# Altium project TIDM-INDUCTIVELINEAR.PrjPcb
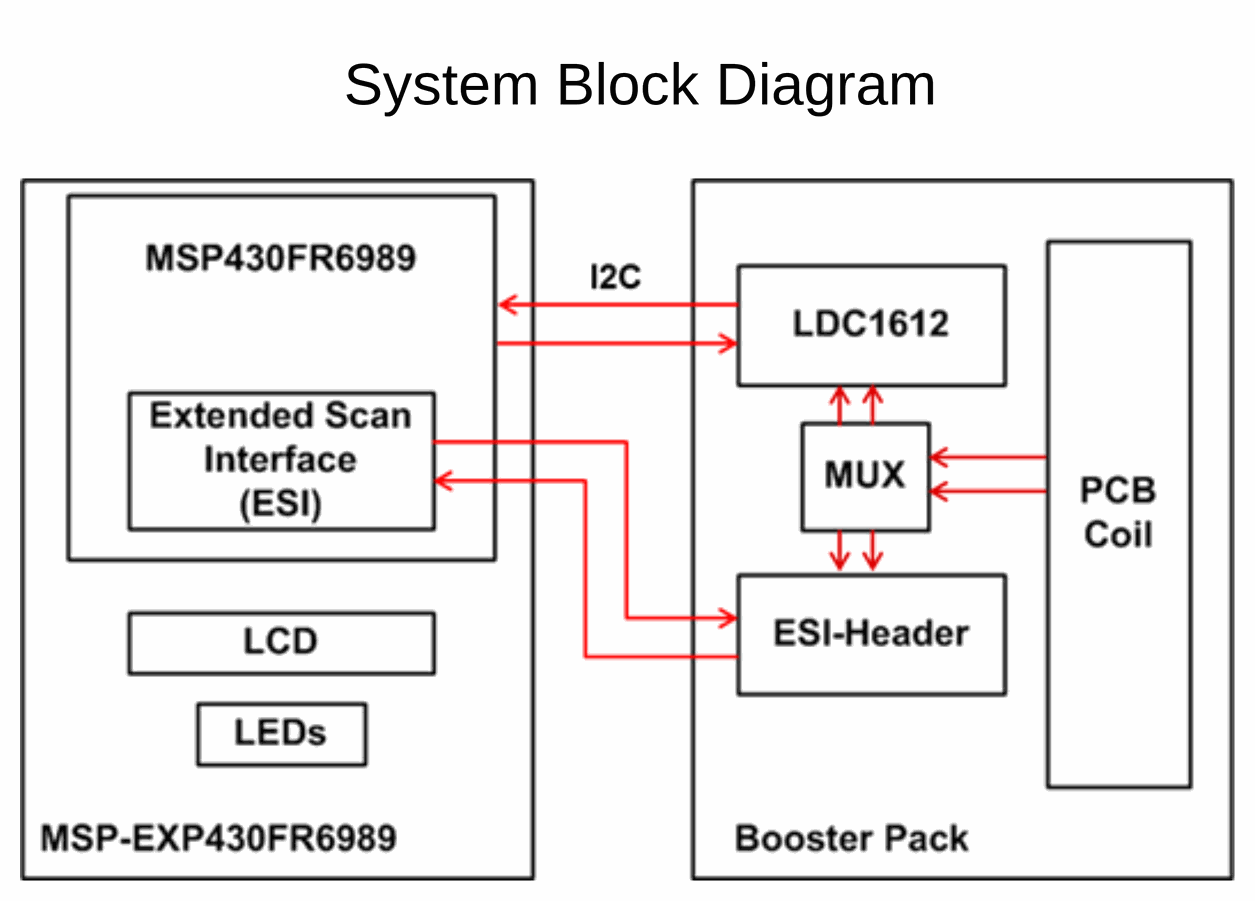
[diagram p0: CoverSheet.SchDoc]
CopyrightYear: 2015; EVM_Orderable: N/A; PCB_Layout: a0225755; PCB_Rev: 1.0; PRJ_Customer: Public Release; PRJ_Engineer: a0225755; PRJ_TITLE: TIDM_INDUCTIVELINEAR; SCH_Rev: 1.0; TechSupport: http://www.ti.com/support; TID: TIDM-INDUCTIVELINEAR
2 sheets, 26 parts. Net scope: global (net labels, ports and power ports of the same name join across sheets).
Board file: TIDM-INDUCTIVELINEAR.PcbDoc
Sheets:
  CoverSheet.SchDoc
  Schematics.SchDoc

## Sheet CoverSheet.SchDoc
size 431 x 279 mm; Date: Not shown in title block; ApprovedBy: Not shown in title block; CheckedBy: Not shown in title block; Author: Not shown in title block; CompanyName: Not shown in title block; Engineer: Not shown in title block; Organization: Not shown in title block; Address1: Not shown in title block; Address2: Not shown in title block; Address3: Not shown in title block; Address4: Not shown in title block; DocumentNumber: 1; Revision: Use project parameter SCH_Rev; SheetNumber: 1; SheetTotal: 2; PageSetup: Record=PageOptions|CenterHorizontal=True|CenterVertical=True|PrintScale=1.00|XCorrection=1.00|YCorrection=1.00|PrintKind=0|BorderSize=5000000|LeftOffset=0|BottomOffset=0|Orientation=2|PaperLength=1000|PaperWidth=1000|Scale=100|PaperSource=15|PrintQuality=600|MediaType=1|DitherType=10|PaperKind=Letter|PrintScaleMode=1

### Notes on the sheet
- System Block Diagram

## Sheet Schematics.SchDoc
size 431 x 279 mm; VersionControl_RevNumber: Not shown in title block; Date: Not shown in title block; ApprovedBy: Not shown in title block; CheckedBy: Not shown in title block; Author: Not shown in title block; CompanyName: Not shown in title block; Engineer: Not shown in title block; Organization: Not shown in title block; Address1: Not shown in title block; Address2: Not shown in title block; Address3: Not shown in title block; Address4: Not shown in title block; DocumentNumber: 1; Revision: Use project parameter SCH_Rev; SheetNumber: 2; SheetTotal: 2; PageSetup: Record=PageOptions|CenterHorizontal=True|CenterVertical=True|PrintScale=1.00|XCorrection=1.00|YCorrection=1.00|PrintKind=0|BorderSize=5000000|LeftOffset=0|BottomOffset=0|Orientation=2|PaperLength=1000|PaperWidth=1000|Scale=100|PaperSource=15|PrintQuality=600|MediaType=1|DitherType=10|PaperKind=Letter|PrintScaleMode=1
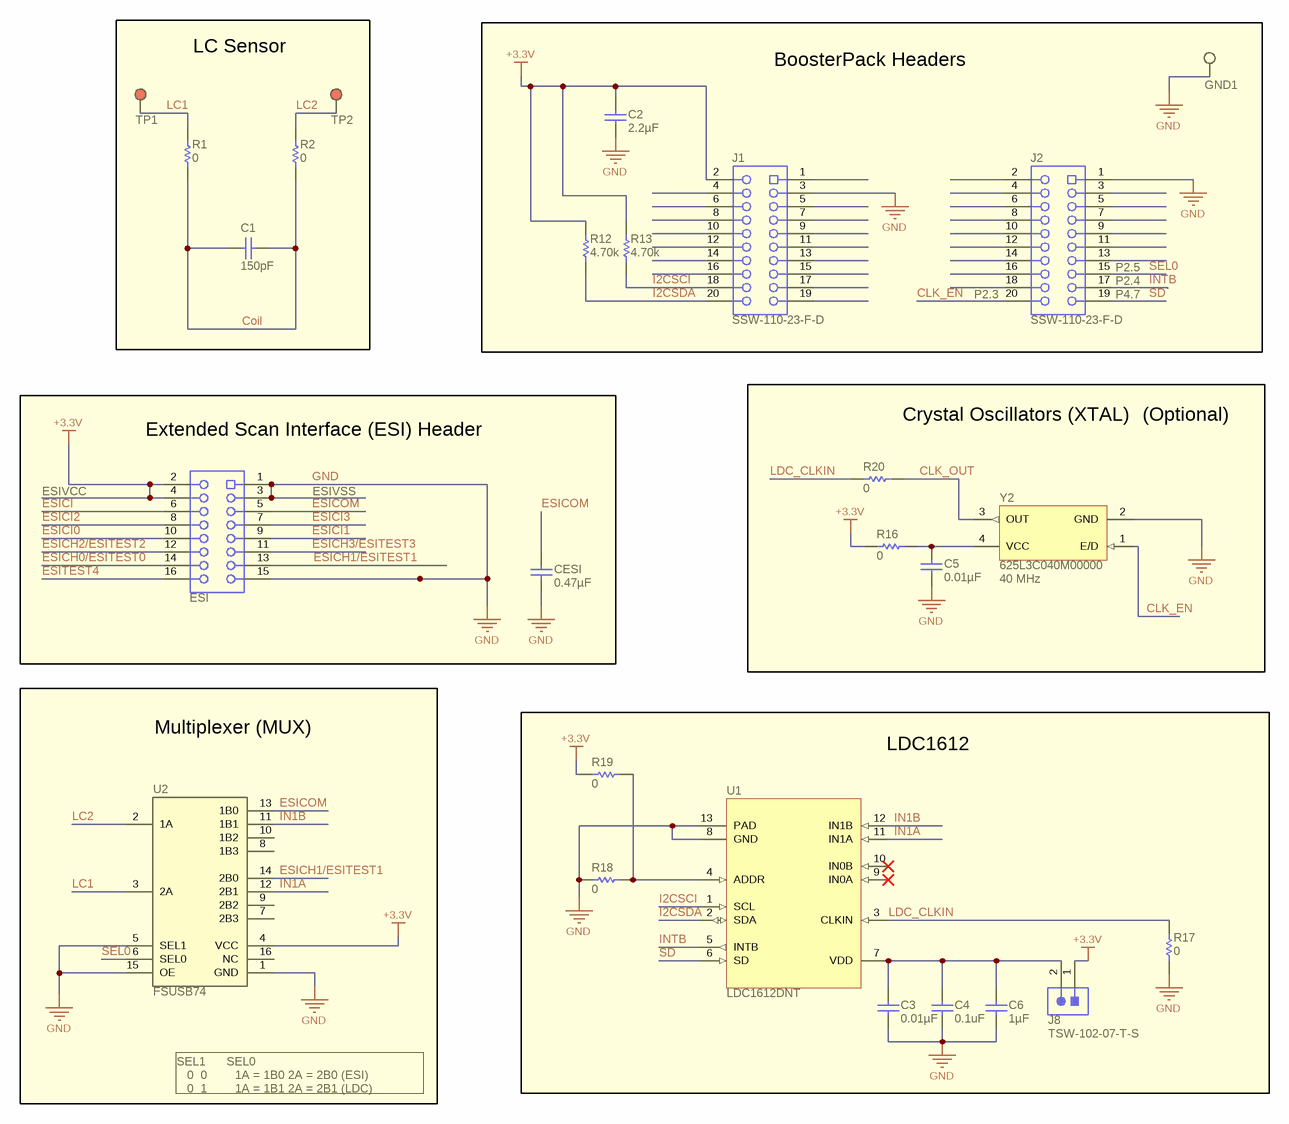
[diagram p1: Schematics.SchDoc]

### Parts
C1  ValueDisplayed: 150pF  [0603]  (hidden comment: GRM1885C2A151JA01D)
C2  ValueDisplayed: 2.2µF  [0603]  (hidden comment: C0603C225K8PACTU)
C3  ValueDisplayed: 0.01µF  [0402]  (hidden comment: C1005X7R1C103K)
C4  value 0.1uF  [0402]  (hidden comment: GRM155R71C104JA88D)
C5  ValueDisplayed: 0.01µF  [0603]  (hidden comment: C1608C0G1E103J)
C6  ValueDisplayed: 1µF  [0402]  (hidden comment: GRM155R61A105KE15D)
CESI  ValueDisplayed: 0.47µF  [0603]  (hidden comment: GRM188R61A474KA61D)
ESI  SSQ-108-02-G-D  [SAMTEC_SSQ-108-02-G-D]  (value not drawn)
GND1  5016  [Testpoint_Keystone_Compact]  (value not drawn)
J1  SSW-110-23-F-D  [CONN_SSW-110-23-F-D]
J2  SSW-110-23-F-D  [CONN_SSW-110-23-F-D]
J8  TSW-102-07-T-S  [Samtec_TSW-102-07-T-S]
R1  ValueDisplayed: 0  [0805_HV]  (hidden comment: ERJ-6GEY0R00V)
R2  ValueDisplayed: 0  [0805_HV]  (hidden comment: ERJ-6GEY0R00V)
R12  value 4.70k  [0603]  (hidden comment: RC0603FR-074K7L)
R13  value 4.70k  [0603]  (hidden comment: RC0603FR-074K7L)
R16  value 0  [0603]  (hidden comment: CRCW06030000Z0EA)
R17  value 0  [0603]  (hidden comment: CRCW06030000Z0EA)
R18  value 0  [0603]  (hidden comment: CRCW06030000Z0EA)
R19  value 0  [0603]  (hidden comment: CRCW06030000Z0EA)
R20  value 0  [0603]  (hidden comment: CRCW06030000Z0EA)
TP1  5000  [Keystone5000]  (value not drawn)
TP2  5000  [Keystone5000]  (value not drawn)
U1  LDC1612DNT  [DNT0012B]
U2  FSUSB74  [LCCS40P210X290X55-16N]
Y2  625L3C040M00000  Frequency: 40 MHz  [OSC_CTS_625]

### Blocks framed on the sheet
LC Sensor: C1 R1 R2 TP1 TP2
BoosterPack Headers: C2 GND1 J1 J2 R12 R13
Extended Scan Interface (ESI) Header: CESI ESI
Multiplexer (MUX): U2
LDC1612: C3 C4 C6 J8 R17-R19 U1

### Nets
+3.3V: C2.1 ESI.2 ESI.4 J1.2 J8.1 R12.2 R13.2 R16.2 R19.2 U2.4(VCC)
GND: C2.2 C3.2 C4.2 C5.2 C6.2 CESI.2 ESI.1 ESI.3 ESI.15 GND1.1 J1.3 J2.1 R17.2 R18.2 U1.8(GND) U1.13(PAD) U2.1(GND) U2.5(SEL1) U2.15(OE) Y2.2(GND)
CLK_EN: J2.20 Y2.1(E/D)
CLK_OUT: R20.1 Y2.3(OUT)
Coil: C1.1 C1.2 R1.1 R2.1
ESICH0/ESITEST0: ESI.14
ESICH1/ESITEST1: ESI.13 U2.14(2B0)
ESICH2/ESITEST2: ESI.12
ESICH3/ESITEST3: ESI.11
ESICI: ESI.6
ESICI0: ESI.10
ESICI1: ESI.9
ESICI2: ESI.8
ESICI3: ESI.7
ESICOM: CESI.1 ESI.5 U2.13(1B0)
ESITEST4: ESI.16
I2CSCI: J1.18 R13.1 U1.1(SCL)
I2CSDA: J1.20 R12.1 U1.2(SDA)
IN1A: U1.11(IN1A) U2.12(2B1)
IN1B: U1.12(IN1B) U2.11(1B1)
INTB: J2.17 U1.5(INTB)
LC1: R1.2 TP1.1 U2.3(2A)
LC2: R2.2 TP2.1 U2.2(1A)
LDC_CLKIN: R17.1 R20.2 U1.3(CLKIN)
SD: J2.19 U1.6(SD)
SEL0: J2.15 U2.6(SEL0)
NetC3_1: C3.1 C4.1 C6.1 J8.2 U1.7(VDD)
NetC5_1: C5.1 R16.1 Y2.4(VCC)
NetR18_1: R18.1 R19.1 U1.4(ADDR)

Not connected (* = marked no-connect by the designer): J1 1 4 5 6 7 8 9 10 11 12 13 14 15 16 17 19; J2 2 3 4 5 6 7 8 9 10 11 12 13 14 16 18; U1 9(IN0A)* 10(IN0B)*; U2 7(2B3) 8(1B3) 9(2B2) 10(1B2) 16(NC)

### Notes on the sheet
- (near J2) P2.4
- (near J2) P2.5
- (near J2) P2.3
- (near J2) P4.7
- Crystal Oscillators (XTAL)
- (Optional)
- ESIVCC
- ESIVSS
- SEL1      SEL0
  0	 0        1A = 1B0 2A = 2B0 (ESI)
  0	 1        1A = 1B1 2A = 2B1 (LDC)

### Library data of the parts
C1 = GRM1885C2A151JA01D: CAP, CERM, 150 pF, 100 V, +/- 5%, C0G/NP0, 0603; Manufacturer: MuRata; Polarized: N; CompType: Capacitor; Value: 150pF; U/M: EA; Cap_F: 0.00000000015; Tolerance_%: 5; Value1: Unknown; VDC_V: 100; Value2: 100V; TaMin_C: -55; TaMax_C: 125
C2 = C0603C225K8PACTU: CAP, CERM, 2.2uF, 10V, +/-10%, X5R, 0603; Manufacturer: Kemet; Polarized: N; CompType: Capacitor; U/M: EA; Cap_F: 0.0000022; Tolerance_%: 10; Value1: Unknown; TaMin_C: -55; TaMax_C: 85
C3 = C1005X7R1C103K: CAP, CERM, 0.01 µF, 16 V, +/- 10%, X7R, 0402; Manufacturer: TDK; Polarized: N; CompType: Capacitor; Value: 0.01uF; U/M: EA; Cap_F: 0.00000001; Tolerance_%: 10; ESR_ohm: 0.0623; Value1: 0.0623 ohm; VDC_V: 16; Value2: 16V; TaMin_C: -55; TaMax_C: 125
C4 = 0402YC132KAT2A: CAP CER 0.1UF 16V 5% X7R 0402; Manufacturer: Murata Electronics North America; Polarized: N; CompType: Capacitor; U/M: EA; Cap_F: 0.0000000013; Tolerance_%: 10; VDC_V: 16; TaMin_C: -55; TaMax_C: 125
C5 = C1608C0G1E103J: CAP, CERM, 0.01uF, 25V, +/-5%, C0G/NP0, 0603; Manufacturer: TDK; Polarized: N; CompType: Capacitor; U/M: EA; Cap_F: 0.00000001; Tolerance_%: 5; VDC_V: 25; TaMin_C: -55; TaMax_C: 125
C6 = GRM155R61A105KE15D: CAP, CERM, 1uF, 10V, +/-10%, X5R, 0402; Manufacturer: MuRata; Polarized: N; CompType: Capacitor; U/M: EA; Cap_F: 0.000001; Tolerance_%: 10; Value1: Unknown; TaMin_C: -55; TaMax_C: 85
CESI = GRM188R61A474KA61D: CAP, CERM, 0.47 µF, 10 V, +/- 10%, X5R, 0603; Manufacturer: MuRata; Polarized: N; CompType: Capacitor; Value: 0.47uF; U/M: EA; Cap_F: 0.00000047; Tolerance_%: 10; Value1: Unknown; Value2: 10V; TaMin_C: -55; TaMax_C: 85
ESI = SSQ-108-02-G-D: Receptacle, 100mil, 8x2, Gold, TH; Manufacturer: Samtec; SymbolCreator: a0411947; U/M: EA
GND1 = 5016: Test Point, Compact, SMT; Manufacturer: Keystone; CompType: Test Point Loop; U/M: EA
J1 J2 = SSW-110-23-F-D: Connector, Receptacle, 100mil, 10x2, Gold plated, TH; Manufacturer: Samtec; SymbolCreator: a0412235; U/M: EA
J8 = TSW-102-07-T-S: Header, 2.54 mm, 2x1, Tin, TH; Manufacturer: Samtec; SymbolCreator: a0412235; U/M: EA
R1 R2 = ERJ-6GEY0R00V: RES, 0, 5%, 0.125 W, 0805; Manufacturer: Panasonic; CompType: Resistor; Value: 0; Value_Code: 0000; Tolerance_%: 5; Power_W: 0.125; Value2: 0.125W; VDC_V: 150; TempCo: 600 ppm/C; EIA_Code: E24; U/M: EA
R12 R13 = RC0603FR-074K7L: RES, 4.70k ohm, 1%, 0.1W, 0603; Manufacturer: Yageo America; CompType: Resistor; Res_ohm: 4700; Value_Code: 4k70; Tolerance_%: 1; Power_W: 0.1; VDC_V: 150; TempCo: 200 ppm/C; U/M: EA
R16-R20 = CRCW06030000Z0EA: RES, 0 ohm, 5%, 0.1W, 0603; Manufacturer: Vishay-Dale; CompType: Resistor; Value_Code: 0000; Tolerance_%: 5; Power_W: 0.1; VDC_V: 75; TempCo: 200 ppm/C; EIA_Code: E24; U/M: EA
TP1 TP2 = 5000: Test Point, Miniature, Red, TH; Manufacturer: Keystone; CompType: Test Point Loop; U/M: EA
U1 = LDC1612DNT: Multi-Channel 12/28-Bit Inductance to Digital Converter with I2C, DNT0012B; Manufacturer: Texas Instruments; SymbolCreator: a0411947; CompType: IC; U/M: EA
U2 = FSUSB74: MUX; Manufacturer: Used in BOM report; SymbolVersion: use current date i.e. 2008-05-20; SymbolCreator: Use a-id; CompType: Used in some BOM reports.  Useful for finding later.; U/M: EA, IN, or GM
Y2 = 625L3C040M00000: OSC, 40 MHz, 3.3 V, SMD; Manufacturer: CTS Electrocomponents; SymbolCreator: a0411947; CompType: Oscillator; U/M: EA; TaMin_C: -20; TaMax_C: 70; Frequency Stability: ±50ppm

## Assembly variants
TI Design: all parts fitted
